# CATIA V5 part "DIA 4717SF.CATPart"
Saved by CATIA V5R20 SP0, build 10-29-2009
Part number: DIA 4717SF
Revision: ANY
Definition: UNKNOWN
Nomenclature: DIA 4717SF
Source: Unknown
Bounding box of the stored display mesh (mm): x -2.35 to 2.35, y -7.925 to 9.045, z -2.35 to 2.35
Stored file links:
  C:\Users\Utente\Desktop\IO LAVORO\3D X SITO CF\CUMSA\3D files FA\FA 084705-21\DIA 4717SF.CATPart
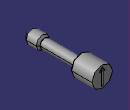
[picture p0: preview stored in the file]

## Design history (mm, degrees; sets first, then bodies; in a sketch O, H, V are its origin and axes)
Body1 "Cortar-Extruir2" (main body)
  Solid1: solid without history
